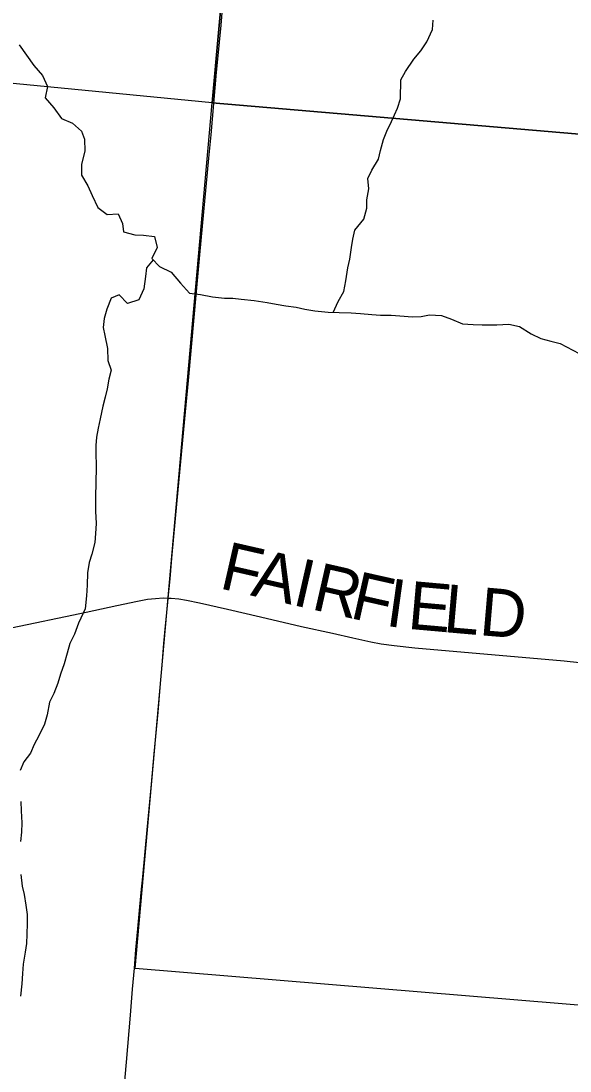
# Model space of a CAD drawing. Extents: x 0 to 1134, y 0 to 440.
# Drawn here: x 841.162 to 841.812, y 357.243 to 358.485 of the extents above; entities that cross this region are included whole.
import ezdxf

# ---------------------------------------------------------------- set-up
doc = ezdxf.new("R2010")
doc.units = 0
for name, color, linetype in [('GM_X_County_Road', 7, 'Continuous'), ('GM_X_County_Road_Text', 7, 'Continuous'), ('GM_X_Minor_River', 7, 'Continuous'), ('GM_X_Section', 7, 'Continuous'), ('GM_X_Township_Road', 7, 'Continuous')]:
    doc.layers.add(name, color=color, linetype=linetype)

msp = doc.modelspace()

# ---------------------------------------------------------------- linework, layer by layer
at = {"layer": 'GM_X_County_Road'}
for points in [[(841.087, 357.7537), (841.0904, 357.7543), (841.1237, 357.7615), (841.215, 357.7806), (841.2393, 357.7855), (841.2757, 357.7935), (841.3, 357.7987), (841.3122, 357.8009), (841.3214, 357.802), (841.3306, 357.8026), (841.3365, 357.8024)], [(841.3365, 357.8024), (841.3399, 357.8023), (841.3491, 357.8013), (841.3582, 357.7999), (841.3734, 357.7967), (841.4067, 357.7892), (841.446, 357.78), (841.4945, 357.7689), (841.5309, 357.7608), (841.5551, 357.7552), (841.5763, 357.7504), (841.5886, 357.7482), (841.604, 357.7461), (841.6287, 357.7434), (841.6875, 357.7384), (841.7556, 357.7325), (841.8052, 357.7281), (841.8237, 357.7261)]]:
    msp.add_lwpolyline(points, dxfattribs=at)
at = {"layer": 'GM_X_Minor_River'}
for points in [[(841.5319, 358.1405), (841.5378, 358.1535), (841.5444, 358.1652), (841.5468, 358.178), (841.5493, 358.1932), (841.5517, 358.2037), (841.5534, 358.2174), (841.555, 358.2272), (841.5574, 358.2378), (841.5681, 358.2509), (841.5717, 358.2637), (841.5718, 358.2736), (841.5739, 358.2868), (841.5729, 358.299), (841.5776, 358.3088), (841.5857, 358.3219), (841.588, 358.3321), (841.5916, 358.3453), (841.5955, 358.3551), (841.6009, 358.3664), (841.6079, 358.3823), (841.6115, 358.3932), (841.6118, 358.4159), (841.6176, 358.4257), (841.6272, 358.4404), (841.6356, 358.4501), (841.6429, 358.4607), (841.6495, 358.4753), (841.6501, 358.4863)], [(841.1602, 358.4571), (841.1773, 358.4327), (841.1877, 358.4208), (841.1936, 358.4078), (841.1908, 358.3946), (841.2012, 358.3827), (841.2102, 358.3701), (841.2233, 358.3643), (841.2338, 358.355), (841.2374, 358.3455), (841.238, 358.3315), (841.2337, 358.316), (841.2339, 358.3031), (841.2413, 358.2905), (841.2464, 358.2787), (841.2531, 358.2646), (841.2643, 358.2562), (841.2772, 358.2571), (841.2823, 358.2457), (841.2837, 358.2358), (841.2969, 358.2323), (841.3071, 358.2318), (841.3203, 358.2305), (841.3236, 358.2175), (841.3173, 358.2043), (841.3263, 358.1948), (841.3402, 358.1882), (841.351, 358.1751), (841.3618, 358.1633), (841.3746, 358.1616), (841.389, 358.1591), (841.4033, 358.1574), (841.4131, 358.1573), (841.423, 358.1561), (841.4384, 358.1544), (841.4539, 358.1523), (841.4645, 358.1502), (841.4758, 358.1482), (841.4879, 358.1465), (841.4984, 358.1445), (841.5101, 358.1425), (841.526, 358.1408), (841.5388, 358.1402), (841.5532, 358.1401), (841.5641, 358.1392), (841.5777, 358.1379), (841.5879, 358.1374), (841.6004, 358.1372), (841.6106, 358.1363), (841.6257, 358.1354), (841.6359, 358.1356), (841.6461, 358.1378), (841.6601, 358.1369), (841.6721, 358.1325), (841.6849, 358.1271), (841.6978, 358.1262), (841.7083, 358.1257), (841.7257, 358.1258), (841.7397, 358.1264), (841.7525, 358.124), (841.7664, 358.1151), (841.7777, 358.1096), (841.7894, 358.1065), (841.8007, 358.1037), (841.8232, 358.092)], [(841.3187, 358.2029), (841.3108, 358.1931), (841.3095, 358.1828), (841.3078, 358.1685), (841.3016, 358.1553), (841.2883, 358.1509), (841.2786, 358.1613), (841.2688, 358.1572), (841.2637, 358.1444), (841.2609, 358.1334), (841.2596, 358.1225), (841.2614, 358.113), (841.2646, 358.0978), (841.2652, 358.0837), (841.2688, 358.0723), (841.2664, 358.0614), (841.2644, 358.05), (841.262, 358.0402), (841.2592, 358.0296), (841.256, 358.0145), (841.2536, 358.0036), (841.2516, 357.993), (841.2507, 357.9828), (841.251, 357.9729), (841.2512, 357.9596), (841.2509, 357.9365), (841.2504, 357.9248), (841.2506, 357.9153), (841.2505, 357.9051), (841.2511, 357.8907), (841.2506, 357.8786), (841.2497, 357.868), (841.2461, 357.8544), (841.243, 357.8445), (841.2409, 357.8324), (841.2407, 357.8177), (841.2398, 357.8052), (841.2381, 357.7897), (841.2304, 357.7727), (841.2257, 357.7595), (841.2202, 357.7486), (841.2167, 357.7373), (841.2135, 357.7244), (841.2092, 357.7123), (841.206, 357.7018), (841.2013, 357.6893), (841.1959, 357.6792), (841.1931, 357.664), (841.1899, 357.6531), (841.1833, 357.6392), (841.1779, 357.629), (841.1733, 357.6188), (841.1656, 357.6087), (841.1613, 357.5981)], [(841.162, 357.5617), (841.1626, 357.5507), (841.1632, 357.5363), (841.1627, 357.5254), (841.1618, 357.5144)], [(841.162, 357.4753), (841.1637, 357.4613), (841.1659, 357.4514), (841.168, 357.4389), (841.1694, 357.4279), (841.1696, 357.4173), (841.1691, 357.4044), (841.1686, 357.3934), (841.1673, 357.3832), (841.1649, 357.3692), (841.164, 357.3578), (841.1631, 357.3457), (841.1618, 357.3313)]]:
    msp.add_lwpolyline(points, dxfattribs=at)
at = {"layer": 'GM_X_Section'}
for points in [[(841.4628, 359.3584), (841.4764, 359.357), (841.3884, 358.3886), (840.3845, 358.4859), (840.4745, 359.4562)], [(841.4764, 359.357), (842.4578, 359.2752), (842.4696, 359.2746), (842.4019, 358.3021), (841.3884, 358.3886)], [(841.3884, 358.3886), (842.4019, 358.3021), (842.3134, 357.2799), (841.2975, 357.3638)]]:
    msp.add_lwpolyline(points, close=True, dxfattribs=at)
at = {"layer": 'GM_X_Township_Road'}
for points in [[(841.3365, 357.8024), (841.3387, 357.825), (841.341, 357.8497), (841.3473, 357.9177), (841.3514, 357.9642), (841.357, 358.0229), (841.3605, 358.06), (841.3672, 358.1343), (841.37, 358.1652), (841.3739, 358.2085), (841.3847, 358.323), (841.3873, 358.3508), (841.3921, 358.4064), (841.3938, 358.425), (841.3952, 358.4404), (841.3992, 358.4806), (841.4014, 358.5054)], [(841.2844, 357.222), (841.287, 357.2529), (841.2902, 357.29), (841.2917, 357.3086), (841.2943, 357.3396), (841.2965, 357.3643), (841.2981, 357.3858), (841.3006, 357.4107), (841.3025, 357.4324), (841.3045, 357.454), (841.3063, 357.4725), (841.3117, 357.5282), (841.3162, 357.5777), (841.3201, 357.6179), (841.3247, 357.6674), (841.3275, 357.7014), (841.3293, 357.723), (841.3314, 357.7484), (841.3335, 357.7694), (841.336, 357.7972), (841.3365, 357.8024)]]:
    msp.add_lwpolyline(points, dxfattribs=at)

# ---------------------------------------------------------------- texts
at = {"layer": 'GM_X_County_Road_Text'}
for s, rotation, p in [('F', 347.1566, (841.3957, 357.8142)), ('A', 347.1557, (841.433, 357.8057)), ('I', 347.1528, (841.4818, 357.7946)), ('R', 347.1626, (841.5045, 357.7894)), ('F', 347.3404, (841.5502, 357.779)), ('I', 352.0602, (841.5926, 357.7697)), ('E', 354.9353, (841.6189, 357.7661)), ('L', 354.9784, (841.6612, 357.7623)), ('D', 355.1452, (841.7038, 357.7586))]:
    msp.add_text(s, height=0.0568, rotation=rotation, dxfattribs=at).set_placement(p)

doc.saveas('drawing.dxf')
